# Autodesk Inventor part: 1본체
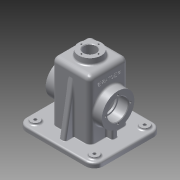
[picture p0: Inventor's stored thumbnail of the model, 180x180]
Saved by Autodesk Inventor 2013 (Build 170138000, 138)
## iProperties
Created: 2016-01
Part Number: 1본체
Material: 알루미늄 6061
Document SubType Name: Modeling
Designer: Administrator
Density: 2.71 g/cm^3
Mass: 810.011 g
Surface Area: 906.161 cm^2
Volume: 298.897 cm^3
Author: Administrator
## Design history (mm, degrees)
sketch "스케치1"
  geometry: L1 (-65, 57.5)-(65, 57.5); L2 (65, 57.5)-(65, -57.5); L3 (65, -57.5)-(-65, -57.5); L4 (-65, -57.5)-(-65, 57.5); 3 further points
  constraints: 8 end point, 2 midpoint, 2 parallel, 1 horizontal, 1 horizontal alignment, 1 perpendicular, 1 vertical alignment
  dimensions: "d0" = 130 distance of L1.start L1.end; "d2" = 115 distance of L1.end L2.end
extrude "돌출1" new body sketch "스케치1" distance "d3" = 8; taper "d4" = 0 deg
sketch "스케치2"
  geometry: L1 (-60, -52.5)-(60, -52.5); L2 (60, -52.5)-(60, 52.5); L3 (60, 52.5)-(-60, 52.5); L4 (-60, 52.5)-(-60, -52.5); 3 further points
  constraints: 8 end point, 2 midpoint, 2 parallel, 1 horizontal, 1 horizontal alignment, 1 perpendicular, 1 vertical alignment
  dimensions: "d5" = 120 distance of L1.start L1.end; "d7" = 105 distance of L3.end L1.start
extrude "돌출2" join sketch "스케치2" distance "d8" = 2; taper "d9" = 0 deg
fillet "모깎기1" dims "d10" = 10
fillet "모깎기2" dims "d11" = 15
sketch "스케치3"
  geometry: C1 r 7.5 at (-50, 42.5); C2 r 7.5 at (-50, -42.5); C3 r 7.5 at (50, -42.5); C4 r 7.5 at (50, 42.5); A1 r 15 centre (-50, -42.5) between (-65, -42.5) and (-50, -57.5) reference; A2 r 15 centre (50, -42.5) between (50, -57.5) and (65, -42.5) reference; A3 r 15 centre (50, 42.5) between (65, 42.5) and (50, 57.5) reference; A4 r 15 centre (-50, 42.5) between (-50, 57.5) and (-65, 42.5) reference; 1 further point
  constraints: 4 centre point, 4 coincident
  dimensions: "d12" = 15 diameter of C1; "d13" = 15 diameter of C2; "d14" = 15 diameter of C3; "d15" = 15 diameter of C4
extrude "돌출3" join sketch "스케치3" distance "d16" = 3; taper "d17" = 0 deg
hole "구멍1" diameter "d20" = 5; stored, may be unused: countersink angle "d24" = 90 deg, drill point angle "d26" = 118 deg; dims "d18" = 10, "d19" = 10, "d21" = 6, "d22" = 4, "d23" = 2, "d25" = 8
hole "구멍2" diameter "d29" = 5; stored, may be unused: countersink angle "d33" = 90 deg, drill point angle "d35" = 118 deg; dims "d27" = 10, "d28" = 10, "d30" = 6, "d31" = 4, "d32" = 2, "d34" = 8
hole "구멍3" diameter "d38" = 5; stored, may be unused: countersink angle "d42" = 90 deg, drill point angle "d44" = 118 deg; dims "d36" = 10, "d37" = 10, "d39" = 6, "d40" = 4, "d41" = 2, "d43" = 8
hole "구멍4" diameter "d47" = 5; stored, may be unused: countersink angle "d51" = 90 deg, drill point angle "d53" = 118 deg; dims "d45" = 10, "d46" = 10, "d48" = 6, "d49" = 4, "d50" = 2, "d52" = 8
sketch "스케치4"
  geometry: L1 (-32.5, 32.5)-(32.5, 32.5); L2 (32.5, 32.5)-(32.5, -32.5); L3 (32.5, -32.5)-(-32.5, -32.5); L4 (-32.5, -32.5)-(-32.5, 32.5); 3 further points
  constraints: 8 end point, 2 midpoint, 2 parallel, 1 horizontal, 1 horizontal alignment, 1 perpendicular, 1 vertical alignment
  dimensions: "d54" = 65 distance of L1.start L1.end; "d56" = 65 distance of L1.end L2.end
extrude "돌출4" join sketch "스케치4" distance "d57" = 100; taper "d58" = 0 deg
sketch "스케치9"
  geometry: L1 (52.5, -2)-(-52.5, -2) reference; L2 (-52.5, -2)-(-52.5, 0) reference; L3 (-52.5, 0)-(-57.5, 0) reference; L4 (-57.5, 0)-(-57.5, 8) reference; L5 (-57.5, 8)-(-32.5, 8) reference; L6 (-32.5, 8)-(-32.5, 108) reference; L7 (-32.5, 108)-(32.5, 108) reference; L8 (32.5, 108)-(32.5, 8) reference; L9 (32.5, 8)-(57.5, 8) reference; L10 (57.5, 8)-(57.5, 0) reference; L11 (57.5, 0)-(52.5, 0) reference; L12 (52.5, 0)-(52.5, -2) reference; L13 (-42.5, -2)-(42.5, -2) reference; L14 (-27.5, 103)-(27.5, 103); L15 (27.5, 103)-(27.5, -2); L16 (27.5, -2)-(-27.5, -2); L17 (-27.5, -2)-(-27.5, 103); 1 further point
  constraints: 8 end point, 2 parallel, 1 horizontal, 1 perpendicular, 1 point on line
  dimensions: "d78" = 5 distance between parallel lines of L8 L15; "d79" = 5 distance between parallel lines of L6 L17; "d80" = 5 distance between parallel lines of L7 L14
extrude "돌출8" cut sketch "스케치9" stored distance "d81" = 55; taper "d82" = 0 deg
sketch "스케치6"
  geometry: L1 (10, 85)-(10, 75) reference; L2 (0, -10)-(0, 75) reference; C1 r 27.5 at (-45, 32.5); 2 further points
  constraints: 1 centre point, 1 horizontal alignment, 1 midpoint
  dimensions: "d63" = 55 diameter of C1; "d65" = 55 distance from line of C1.centre L1
extrude "돌출5" join sketch "스케치6" distance "d66" = 15; taper "d67" = 0 deg
sketch "스케치7"
  geometry: C1 r 20 at (0, 0); 1 further point
  constraints: 1 centre point, 1 coincident
  dimensions: "d68" = 40 diameter of C1
extrude "돌출6" join sketch "스케치7" distance "d69" = 10; taper "d70" = -5 deg
sketch "스케치8"
  geometry: L1 (-47.5, 8)-(-30.996, 101.599); L2 (-30.996, 101.599)-(-30.996, 8); L3 (-57.5, 0)-(-57.5, 8) reference; L4 (-30.996, 8)-(-47.5, 8); L5 (-57.5, 8)-(-42.5, 8) reference; 1 further point
  constraints: 6 end point, 1 point on line, 1 vertical
  dimensions: "d71" = 10 deg angle of L3 L1; "d73" = 10 distance of L3.end L1.start; "d74" = 16.50407 distance of L2.end L1.start; "d75" = 93.59922 distance of L1.end L2.end
extrude "돌출7" join sketch "스케치8" stored distance "d76" = 10; taper "d77" = 0 deg
hole "구멍5" diameter "d85" = 21; stored, may be unused: countersink angle "d89" = 90 deg, drill point angle "d91" = 118 deg; dims "d83" = 10, "d84" = 10, "d86" = 6, "d87" = 4, "d88" = 2, "d90" = 8
hole "구멍6" diameter "d94" = 30; stored, may be unused: countersink angle "d98" = 90 deg, drill point angle "d100" = 0 deg; dims "d92" = 10, "d93" = 10, "d95" = 6, "d96" = 35, "d97" = 17, "d99" = 8
hole "구멍7" diameter "d103" = 30; stored, may be unused: countersink angle "d107" = 90 deg, drill point angle "d109" = 0 deg; dims "d101" = 10, "d102" = 10, "d104" = 6, "d105" = 35, "d106" = 17, "d108" = 8
sketch "스케치10"
  geometry: C1 r 10.5 at (0, 0) reference; 1 further point
  constraints: 1 horizontal alignment
  dimensions: "d110" = 14.5 distance of point (14.5, 0) C1.centre
hole "구멍8" sketch "스케치10" at (14.5, 0) diameter "d111" = 2.459; stored, may be unused: countersink angle "d115" = 90 deg, drill point angle "d117" = 118 deg; dims "d112" = 7, "d113" = 35, "d114" = 17, "d116" = 9
sketch "스케치11"
  geometry: C1 r 17.5 at (0, 0) reference; 2 further points
  constraints: 1 horizontal alignment
  dimensions: "d121" = 21 distance of point (21, 0) C1.centre
hole "구멍9" sketch "스케치11" at (21, 0) diameter "d122" = 3.242; stored, may be unused: countersink angle "d126" = 90 deg, drill point angle "d128" = 118 deg; dims "d123" = 8, "d124" = 35, "d125" = 17, "d127" = 10
sketch "스케치12"
  geometry: L1 (27.5, 103)-(27.5, -2) reference; L2 (32.5, 8)-(32.5, 108) reference; L3 (42.5, 8)-(32.5, 8); L4 (32.5, 8)-(32.5, 27.958); L5 (32.5, 27.958)-(42.5, 27.958); L6 (42.5, 27.958)-(42.5, 8); L7 (-50, 8)-(50, 8) reference; 1 further point
  constraints: 8 end point, 2 parallel, 1 collinear, 1 horizontal, 1 perpendicular, 1 point on line
  dimensions: "d136" = 15 distance between parallel lines of L6 L1; "d137" = 19.95823 distance of L5.end L3.start
extrude "돌출9" join sketch "스케치12" stored distance "d134" = 10; taper "d135" = 0 deg
fillet "모깎기5" dims "d138" = 8
fillet "모깎기6" dims "d139" = 8
fillet "모깎기7" dims "d140" = 3
fillet "모깎기8" dims "d141" = 3
fillet "모깎기9" dims "d142" = 1
fillet "모깎기10" dims "d143" = 3
fillet "모깎기11" dims "d144" = 3
fillet "모깎기12" dims "d145" = 3
fillet "모깎기13" dims "d146" = 0.3
sketch "스케치14"
  geometry: L1 (-18, 5.375)-(-18, 43.625) reference; A1 r 30.5 centre (47, 24.5) between (28.834, 49) and (28.834, 0) reference; 2 further points
  constraints: 1 horizontal alignment, 1 other
  dimensions: "d148" = 27 distance from line of L1 point (9, 24.5)
feature "엠보싱1" sketch "스케치14" dims "d149" = 0.5, "d150" = 0
fillet "모깎기14" dims "d151" = 3
chamfer "모따기1" distance "d152" = 1; stored, may be unused: second distance "d153" = 2, angle "d154" = 45 deg
node "솔리드1"
mirror "대칭1"
mirror "대칭2"
pattern_circular "원형 패턴1" dims angle "d119" = 360 deg
pattern_circular "원형 패턴2" dims angle "d130" = 360 deg
mirror "대칭3"
mirror "대칭4"
node "절단 모서리 투영1"
